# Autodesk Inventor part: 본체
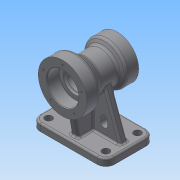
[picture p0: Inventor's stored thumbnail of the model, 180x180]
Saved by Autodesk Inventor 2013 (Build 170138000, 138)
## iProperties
Created: 2015-08
Part Number: 본체
Material: 일반
Document SubType Name: Modeling
Designer: Administrator
Density: 1 g/cm^3
Author: Administrator
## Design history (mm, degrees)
sketch "스케치1"
  geometry: L1 (-47, 40)-(47, 40); L2 (61, 26)-(61, -26); L3 (47, -40)-(-47, -40); L4 (-61, -26)-(-61, 26); A1 r 14 centre (47, -26) between (47, -40) and (61, -26); A2 r 14 centre (47, 26) between (61, 26) and (47, 40); A3 r 14 centre (-47, 26) between (-47, 40) and (-61, 26); A4 r 14 centre (-47, -26) between (-61, -26) and (-47, -40); 6 further points
  constraints: 8 end point, 8 point on circle, 8 tangent, 6 point on line, 4 centre point, 2 midpoint, 2 parallel, 1 horizontal, 1 horizontal alignment, 1 perpendicular, 1 vertical alignment
  dimensions: "d0" = 122 distance of point (-61, 40) point (61, 40); "d2" = 80 distance of point (61, 40) point (61, -40); "d3" = 14 radius of A1; "d4" = 14 radius of A2; "d5" = 14 radius of A3; "d6" = 14 radius of A4
extrude "돌출1" new body sketch "스케치1" distance "d7" = 12; taper "d8" = 0 deg
node "작업 평면2"
sketch "스케치4"
  geometry: L1 (47, 40)-(-47, 40) reference; L2 (0, 40)-(0, -50); L3 (0, 40)-(35, 40); L4 (35, 40)-(35, 20); L5 (35, 20)-(26, 14.804); L6 (26, 14.804)-(26, -13.315); L7 (26, -13.315)-(40, -30); L8 (40, -30)-(40, -50); L9 (40, -50)-(0, -50); 1 further point
  constraints: 16 end point, 3 perpendicular, 2 parallel, 1 midpoint, 1 point on line
  dimensions: "d28" = 90 distance of L2.start L2.end; "d31" = 60 deg angle of L5 L6; "d33" = 40 deg angle of L6 L7; "d35" = 20 distance of L3.end L4.end; "d36" = 20 distance of L7.end L8.end; "d38" = 80 diameter of L8 L2; "d39" = 70 diameter of L4 L2; "d40" = 52 diameter of L6 L2
revolve "회전1" sketch "스케치4" stored, may be unused: angle "d41" = 90 deg
sketch "스케치6"
  geometry: L1 (47, 12)-(-47, 12) reference; L2 (-47, 12)-(-61, 12) reference; L3 (61, 12)-(47, 12) reference; L4 (-25.091, 83.185)-(-51, 12); L5 (25.091, 83.185)-(51, 12); L6 (61, 0)-(61, 12) reference; L7 (-61, 0)-(-61, 12) reference; L8 (-51, 12)-(51, 12); A1 r 26 centre (0, 90) between (-25.091, 83.185) and (25.091, 83.185) reference; A2 r 26 centre (0, 90) between (-25.091, 83.185) and (25.091, 83.185); 1 further point
  constraints: 6 end point, 4 point on circle, 2 point on line, 1 centre point, 1 coincident, 1 perpendicular
  dimensions: "d45" = 10 distance from line of L6 L5.end; "d46" = 10 distance from line of L4.end L7; "d47" = 70 deg angle of L5 L1; "d48" = 70 deg angle of L4 L1
extrude "돌출2" join sketch "스케치6" stored distance "d49" = 12; taper "d50" = 0 deg
sketch "스케치8"
  geometry: L1 (26, 12)-(-26, 12) reference; L2 (-26, 12)-(-40, 12) reference; L3 (40, 12)-(26, 12) reference; L4 (-30, 12)-(-39.698, 67); L5 (-39.698, 67)-(30, 67); L6 (30, 67)-(30, 12); L7 (-40, 0)-(-40, 12) reference; L8 (40, 0)-(40, 12) reference; L9 (-30, 12)-(30, 12); 1 further point
  constraints: 8 end point, 2 point on line, 1 collinear, 1 parallel, 1 perpendicular
  dimensions: "d55" = 10 distance from line of L4.start L7; "d56" = 10 distance between parallel lines of L8 L6; "d57" = 80 deg angle of L4 L1; "d58" = 55 distance between parallel lines of L9 L5
extrude "돌출3" join sketch "스케치8" stored distance "d59" = 12; taper "d60" = 0 deg
sketch "스케치9"
  geometry: L1 (-50, 130)-(-50, 50) reference; L2 (40, 125)-(40, 55) reference; L3 (-50, 90)-(40, 90); L4 (-50, 64)-(-30, 64); L5 (-30, 64)-(-30, 71); L6 (-30, 71)-(-27, 71); L7 (-27, 71)-(-27, 74); L8 (-27, 74)-(23, 74); L9 (23, 74)-(23, 70); L10 (23, 70)-(40, 70); 1 further point
  constraints: 16 end point, 4 perpendicular, 3 parallel, 2 midpoint, 2 point on line
  dimensions: "d61" = 52 diameter of L4 L3; "d64" = 38 diameter of L6 L3; "d65" = 32 diameter of L8 L3; "d66" = 40 diameter of L10 L3; "d67" = 20 distance of L4.start L4.end; "d68" = 3 distance of L5.end L6.end; "d69" = 17 distance of L9.end L10.end
revolve "회전2" sketch "스케치9" stored, may be unused: angle "d70" = 90 deg
sketch "스케치11" dims "d71" = 66
  geometry: C1 r 40 at (0, 0) reference; 3 further points
  constraints: 2 vertical alignment, 1 coincident, 2 other
hole "구멍1" sketch "스케치11" at (0, 33) diameter "d73" = 3.242; stored, may be unused: countersink angle "d77" = 90 deg, drill point angle "d79" = 118 deg; dims "d74" = 10, "d75" = 4, "d76" = 2, "d78" = 13
sketch "스케치12" dims "d83" = 54
  geometry: A1 r 35 centre (0, 0) between (-6, 34.482) and (6, 34.482) reference; 3 further points
  constraints: 2 vertical alignment, 1 coincident, 2 other
hole "구멍2" sketch "스케치12" at (0, -27) diameter "d85" = 3.242; stored, may be unused: countersink angle "d89" = 90 deg, drill point angle "d91" = 118 deg; dims "d86" = 10, "d87" = 4, "d88" = 2, "d90" = 13
sketch "스케치13"
  geometry: L1 (-30, 36)-(-30, 30); L2 (-18, 30)-(-18, 36); L3 (18, 36)-(18, 30); L4 (30, 30)-(30, 36); L5 (-47, 12)-(-61, 12) reference; A1 r 6 centre (-24, 30) between (-30, 30) and (-18, 30); A2 r 6 centre (-24, 36) between (-18, 36) and (-30, 36); A3 r 6 centre (24, 30) between (18, 30) and (30, 30); A4 r 6 centre (24, 36) between (30, 36) and (18, 36); 1 further point
  constraints: 8 end point, 8 point on circle, 8 tangent, 4 centre point, 4 parallel, 2 horizontal alignment, 1 equal radius, 1 vertical
  dimensions: "d95" = 12 distance between parallel lines of L4 L3; "d97" = 18 dimension on A3 A4; "d98" = 48 distance of A3.centre A1.centre; "d99" = 24 horizontal distance of A3.centre point (0, 0); "d100" = 18 distance from line of A1.centre L5
extrude "돌출4" cut sketch "스케치13" distance "d101" = 50; taper "d102" = 0 deg
sketch "스케치14"
  geometry: C1 r 6 at (-47, 26); C2 r 6 at (47, 26); C3 r 6 at (47, -26); C4 r 6 at (-47, -26); 1 further point
  constraints: 4 centre point, 3 equal radius, 2 horizontal alignment, 2 vertical alignment
  dimensions: "d103" = 94 distance of C2.centre C1.centre; "d105" = 47 horizontal distance of point (0, 0) C2.centre; "d106" = 52 distance of C3.centre C2.centre; "d107" = 26 vertical distance of C2.centre point (0, 0); "d108" = 12 diameter of C3
extrude "돌출5" cut sketch "스케치14" distance "d109" = 50; taper "d110" = 0 deg
fillet "모깎기1" dims "d111" = 0.3
fillet "모깎기2" dims "d112" = 5
fillet "모깎기3" dims "d113" = 3
fillet "모깎기4" dims "d114" = 3
fillet "모깎기5" dims "d115" = 3
fillet "모깎기6" dims "d116" = 3
fillet "모깎기7" dims "d117" = 3
fillet "모깎기8" dims "d118" = 3
fillet "모깎기9" dims "d119" = 3
fillet "모깎기10" dims "d120" = 3
fillet "모깎기11" dims "d121" = 3
chamfer "모따기1" distance "d122" = 1; stored, may be unused: second distance "d123" = 2, angle "d124" = 45 deg
sketch "스케치16"
  geometry: L1 (15.261, 17.002)-(56.739, 17.002); L2 (56.739, 17.002)-(56.739, 10.998); L3 (56.739, 10.998)-(15.261, 10.998); L4 (15.261, 10.998)-(15.261, 17.002); L5 (12, 37)-(12, 26) reference; L6 (52.119, 30)-(15, 30) reference; 4 further points
  constraints: 2 midpoint, 1 horizontal alignment, 1 parallel, 1 vertical alignment, 2 other
  dimensions: "d125" = 24 distance from line of point (36, 14) L5; "d126" = 16 distance from line of L6 point (36, 14); "d127" = 44.73948 distance between parallel lines of L2 L5; "d128" = 12.99796 distance between parallel lines of L1 L6
feature "엠보싱1" sketch "스케치16" dims "d0" = 122, "d2" = 80, "d3" = 14, "d4" = 14, "d5" = 14, "d6" = 14, "d129" = 0.5, "d130" = 0
node "솔리드1"
pattern_circular "원형 패턴1" dims angle "d81" = 360 deg
pattern_circular "원형 패턴2" dims angle "d93" = 360 deg
